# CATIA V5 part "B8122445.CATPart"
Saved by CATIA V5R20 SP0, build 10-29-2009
Part number: B8122445
Revision: 9
Definition: design
Nomenclature: B8122445
Source: made
Description: NOT SPECIFIED
Bounding box of the stored display mesh (mm): x -21.5 to 21.5, y -21.5 to 21.5, z -16 to 29
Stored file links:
  C:\Users\Utente\Desktop\3D files B812\B8122445.CATPart
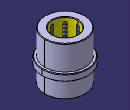
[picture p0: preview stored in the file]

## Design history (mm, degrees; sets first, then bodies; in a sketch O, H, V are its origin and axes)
Body1 "MANIFOLD_SOLID_BREP #38" (main body)
  Solid1: solid without history
Body2 "MANIFOLD_SOLID_BREP #76"
  Solid2: solid without history
Body3 "MANIFOLD_SOLID_BREP #114"
  Solid3: solid without history
Body4 "MANIFOLD_SOLID_BREP #152"
  Solid4: solid without history
Body5 "MANIFOLD_SOLID_BREP #190"
  Solid5: solid without history
Body6 "MANIFOLD_SOLID_BREP #228"
  Solid6: solid without history
Body7 "MANIFOLD_SOLID_BREP #266"
  Solid7: solid without history
Body8 "MANIFOLD_SOLID_BREP #304"
  Solid8: solid without history
Body9 "MANIFOLD_SOLID_BREP #2364"
  Solid9: solid without history
Body10 "MANIFOLD_SOLID_BREP #2402"
  Solid10: solid without history
Body11 "MANIFOLD_SOLID_BREP #2440"
  Solid11: solid without history
Body12 "MANIFOLD_SOLID_BREP #2478"
  Solid12: solid without history
Body13 "MANIFOLD_SOLID_BREP #2516"
  Solid13: solid without history
Body14 "MANIFOLD_SOLID_BREP #2554"
  Solid14: solid without history
Body15 "MANIFOLD_SOLID_BREP #2592"
  Solid15: solid without history
Body16 "MANIFOLD_SOLID_BREP #2630"
  Solid16: solid without history
Body17 "MANIFOLD_SOLID_BREP #2668"
  Solid17: solid without history
Body18 "MANIFOLD_SOLID_BREP #2706"
  Solid18: solid without history
Body19 "MANIFOLD_SOLID_BREP #2744"
  Solid19: solid without history
Body20 "MANIFOLD_SOLID_BREP #2782"
  Solid20: solid without history
Body21 "MANIFOLD_SOLID_BREP #2820"
  Solid21: solid without history
Body22 "MANIFOLD_SOLID_BREP #2858"
  Solid22: solid without history
Body23 "MANIFOLD_SOLID_BREP #2896"
  Solid23: solid without history
Body24 "MANIFOLD_SOLID_BREP #2934"
  Solid24: solid without history
Body25 "MANIFOLD_SOLID_BREP #2972"
  Solid25: solid without history
Body26 "MANIFOLD_SOLID_BREP #3010"
  Solid26: solid without history
Body27 "MANIFOLD_SOLID_BREP #3048"
  Solid27: solid without history
Body28 "MANIFOLD_SOLID_BREP #3086"
  Solid28: solid without history
Body29 "MANIFOLD_SOLID_BREP #3124"
  Solid29: solid without history
Body30 "MANIFOLD_SOLID_BREP #3162"
  Solid30: solid without history
Body31 "MANIFOLD_SOLID_BREP #3200"
  Solid31: solid without history
Body32 "MANIFOLD_SOLID_BREP #3238"
  Solid32: solid without history
Body33 "MANIFOLD_SOLID_BREP #3276"
  Solid33: solid without history
Body34 "MANIFOLD_SOLID_BREP #3314"
  Solid34: solid without history
Body35 "MANIFOLD_SOLID_BREP #3352"
  Solid35: solid without history
Body36 "MANIFOLD_SOLID_BREP #3390"
  Solid36: solid without history
Body37 "MANIFOLD_SOLID_BREP #3428"
  Solid37: solid without history
Body38 "MANIFOLD_SOLID_BREP #3466"
  Solid38: solid without history
Body39 "MANIFOLD_SOLID_BREP #3504"
  Solid39: solid without history
Body40 "MANIFOLD_SOLID_BREP #3542"
  Solid40: solid without history
Body41 "MANIFOLD_SOLID_BREP #3580"
  Solid41: solid without history
Body42 "MANIFOLD_SOLID_BREP #3618"
  Solid42: solid without history
Body43 "MANIFOLD_SOLID_BREP #3656"
  Solid43: solid without history
Body44 "MANIFOLD_SOLID_BREP #3694"
  Solid44: solid without history
Body45 "MANIFOLD_SOLID_BREP #3732"
  Solid45: solid without history
Body46 "MANIFOLD_SOLID_BREP #3770"
  Solid46: solid without history
Body47 "MANIFOLD_SOLID_BREP #3808"
  Solid47: solid without history
Body48 "MANIFOLD_SOLID_BREP #3846"
  Solid48: solid without history
Body49 "MANIFOLD_SOLID_BREP #3884"
  Solid49: solid without history
Body50 "MANIFOLD_SOLID_BREP #3922"
  Solid50: solid without history
Body51 "MANIFOLD_SOLID_BREP #3960"
  Solid51: solid without history
Body52 "MANIFOLD_SOLID_BREP #3998"
  Solid52: solid without history
Body53 "MANIFOLD_SOLID_BREP #4036"
  Solid53: solid without history
Body54 "MANIFOLD_SOLID_BREP #4074"
  Solid54: solid without history
Body55 "MANIFOLD_SOLID_BREP #4112"
  Solid55: solid without history
Body56 "MANIFOLD_SOLID_BREP #4150"
  Solid56: solid without history
Body57 "MANIFOLD_SOLID_BREP #4188"
  Solid57: solid without history
Body58 "MANIFOLD_SOLID_BREP #4226"
  Solid58: solid without history
Body59 "MANIFOLD_SOLID_BREP #4264"
  Solid59: solid without history
Body60 "MANIFOLD_SOLID_BREP #4302"
  Solid60: solid without history
Body61 "MANIFOLD_SOLID_BREP #4340"
  Solid61: solid without history
Body62 "MANIFOLD_SOLID_BREP #4378"
  Solid62: solid without history
Body63 "MANIFOLD_SOLID_BREP #4416"
  Solid63: solid without history
Body64 "MANIFOLD_SOLID_BREP #4454"
  Solid64: solid without history
Body65 "MANIFOLD_SOLID_BREP #4492"
  Solid65: solid without history
Body66 "MANIFOLD_SOLID_BREP #4530"
  Solid66: solid without history
Body67 "MANIFOLD_SOLID_BREP #4568"
  Solid67: solid without history
Body68 "MANIFOLD_SOLID_BREP #4606"
  Solid68: solid without history
Body69 "MANIFOLD_SOLID_BREP #4644"
  Solid69: solid without history
Body70 "MANIFOLD_SOLID_BREP #4682"
  Solid70: solid without history
Body71 "MANIFOLD_SOLID_BREP #4720"
  Solid71: solid without history
Body72 "MANIFOLD_SOLID_BREP #4758"
  Solid72: solid without history
Body73 "MANIFOLD_SOLID_BREP #4796"
  Solid73: solid without history
Body74 "MANIFOLD_SOLID_BREP #4834"
  Solid74: solid without history
Body75 "MANIFOLD_SOLID_BREP #4872"
  Solid75: solid without history
Body76 "MANIFOLD_SOLID_BREP #4910"
  Solid76: solid without history
Body77 "MANIFOLD_SOLID_BREP #4948"
  Solid77: solid without history
Body78 "MANIFOLD_SOLID_BREP #4986"
  Solid78: solid without history
Body79 "MANIFOLD_SOLID_BREP #5024"
  Solid79: solid without history
Body80 "MANIFOLD_SOLID_BREP #5062"
  Solid80: solid without history
Body81 "MANIFOLD_SOLID_BREP #5100"
  Solid81: solid without history
Body82 "MANIFOLD_SOLID_BREP #5138"
  Solid82: solid without history
Body83 "MANIFOLD_SOLID_BREP #5176"
  Solid83: solid without history
Body84 "MANIFOLD_SOLID_BREP #5214"
  Solid84: solid without history
Body85 "MANIFOLD_SOLID_BREP #5252"
  Solid85: solid without history
Body86 "MANIFOLD_SOLID_BREP #5290"
  Solid86: solid without history
Body87 "MANIFOLD_SOLID_BREP #5328"
  Solid87: solid without history
Body88 "MANIFOLD_SOLID_BREP #5366"
  Solid88: solid without history
Body89 "MANIFOLD_SOLID_BREP #5404"
  Solid89: solid without history
Body90 "MANIFOLD_SOLID_BREP #5442"
  Solid90: solid without history
Body91 "MANIFOLD_SOLID_BREP #5480"
  Solid91: solid without history
Body92 "MANIFOLD_SOLID_BREP #5518"
  Solid92: solid without history
Body93 "MANIFOLD_SOLID_BREP #5556"
  Solid93: solid without history
Body94 "MANIFOLD_SOLID_BREP #5594"
  Solid94: solid without history
Body95 "MANIFOLD_SOLID_BREP #5632"
  Solid95: solid without history
Body96 "MANIFOLD_SOLID_BREP #5670"
  Solid96: solid without history
Body97 "MANIFOLD_SOLID_BREP #5708"
  Solid97: solid without history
